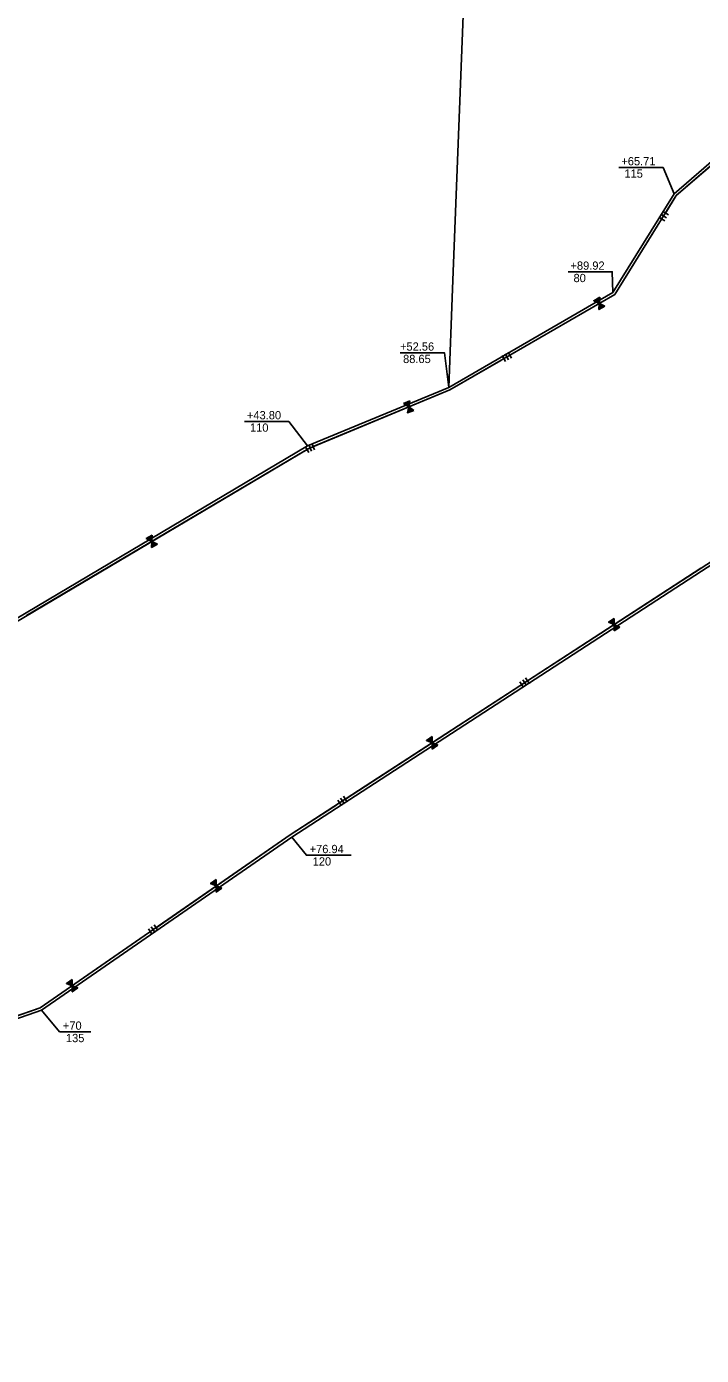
# Model space of a CAD drawing. Extents: x 979729 to 993523, y 1834148 to 1845433.
# Drawn here: x 990587 to 991076, y 1838700 to 1839665 of the extents above; entities that cross this region are included whole.
import ezdxf

# ---------------------------------------------------------------- set-up
doc = ezdxf.new("R2010")
doc.units = 0
for name, color, linetype in [('42', 7, 'Continuous'), ('51', 7, 'Continuous'), ('R_Draft', 7, 'Continuous'), ('S_EXIST_ROW', 7, 'Continuous')]:
    doc.layers.add(name, color=color, linetype=linetype)

msp = doc.modelspace()

# ---------------------------------------------------------------- linework, layer by layer
at = {"layer": '42'}
for p, q in [((991057.83, 1839542.04), (991143.55, 1839616.09)), ((991013.32, 1839470.31), (991057.83, 1839542.04)), ((991046.48, 1839528.48), (991050.73, 1839525.84)), ((991047.8, 1839530.6), (991052.04, 1839527.97)), ((991045.16, 1839526.36), (991049.41, 1839523.72)), ((990893.64, 1839401.08), (991013.32, 1839470.31)), ((990997.95, 1839465.75), (991001.99, 1839463.75)), ((990998.03, 1839465.73), (990998.03, 1839465.8)), ((990998.27, 1839465.63), (990998.29, 1839465.95)), ((990998.51, 1839465.49), (990998.55, 1839466.1)), ((990998.76, 1839465.39), (990998.81, 1839466.25)), ((990999, 1839465.25), (990999.07, 1839466.4)), ((990999.24, 1839465.11), (990999.33, 1839466.55)), ((990999.49, 1839465.01), (990999.59, 1839466.7)), ((990999.73, 1839464.98), (990999.84, 1839466.68)), ((990999.97, 1839464.8), (991000.11, 1839467)), ((991000.22, 1839464.7), (991000.37, 1839467.15)), ((991000.46, 1839464.53), (991000.63, 1839467.3)), ((991000.7, 1839464.46), (991000.89, 1839467.45)), ((991000.94, 1839464.29), (991001.15, 1839467.6)), ((991001.19, 1839464.2), (991001.41, 1839467.75)), ((991001.43, 1839464.05), (991001.67, 1839467.9)), ((991001.67, 1839463.98), (991001.93, 1839468.05)), ((991001.71, 1839459.26), (991001.99, 1839463.75)), ((991001.76, 1839459.87), (991002.31, 1839459.6)), ((991001.76, 1839459.59), (991002.05, 1839459.45)), ((991001.8, 1839460.69), (991003.09, 1839460.06)), ((991001.8, 1839460.41), (991002.83, 1839459.9)), ((991001.8, 1839460.13), (991002.57, 1839459.75)), ((991001.83, 1839460.95), (991003.35, 1839460.21)), ((991001.89, 1839461.48), (991003.87, 1839460.51)), ((991001.9, 1839462.03), (991004.39, 1839460.81)), ((991001.91, 1839463.82), (991002.19, 1839468.2)), ((991001.93, 1839461.74), (991004.13, 1839460.66)), ((991001.93, 1839461.19), (991003.46, 1839460.43)), ((991001.94, 1839462.57), (991004.91, 1839461.11)), ((991001.96, 1839462.28), (991004.65, 1839460.96)), ((991001.97, 1839463.11), (991005.43, 1839461.41)), ((991001.97, 1839462.84), (991005.17, 1839461.26)), ((991001.99, 1839463.75), (991002.28, 1839468.25)), ((991001.99, 1839463.75), (991006.03, 1839461.76)), ((991002.01, 1839463.66), (991005.95, 1839461.71)), ((991002.03, 1839463.36), (991005.69, 1839461.56)), ((991001.73, 1839459.33), (991001.79, 1839459.3)), ((990931.49, 1839425.87), (990933.99, 1839421.54)), ((990933.65, 1839427.12), (990936.16, 1839422.79)), ((990935.82, 1839428.37), (990938.32, 1839424.04)), ((990791.28, 1839358.59), (990893.64, 1839401.08)), ((990861.92, 1839389.99), (990862.34, 1839392.15)), ((990862.14, 1839389.86), (990862.62, 1839392.27)), ((990862.36, 1839389.66), (990862.9, 1839392.38)), ((990862.6, 1839389.56), (990863.17, 1839392.5)), ((990862.81, 1839389.36), (990863.45, 1839392.61)), ((990863.04, 1839389.23), (990863.73, 1839392.73)), ((990863.26, 1839389.06), (990864.01, 1839392.84)), ((990863.49, 1839388.96), (990864.28, 1839392.96)), ((990863.71, 1839388.76), (990864.56, 1839393.07)), ((990863.78, 1839388.69), (990864.65, 1839393.11)), ((990860.04, 1839391.19), (990863.78, 1839388.69)), ((990860.11, 1839391.17), (990860.12, 1839391.23)), ((990860.34, 1839391.04), (990860.4, 1839391.35)), ((990860.56, 1839390.87), (990860.68, 1839391.46)), ((990860.79, 1839390.74), (990860.95, 1839391.58)), ((990861.01, 1839390.57), (990861.23, 1839391.69)), ((990861.23, 1839390.4), (990861.51, 1839391.81)), ((990861.46, 1839390.26), (990861.79, 1839391.92)), ((990861.7, 1839390.2), (990862.03, 1839391.87)), ((990862.91, 1839384.27), (990863.78, 1839388.69)), ((990862.94, 1839384.34), (990863, 1839384.3)), ((990863.01, 1839384.59), (990863.27, 1839384.42)), ((990863.05, 1839384.87), (990863.55, 1839384.53)), ((990863.12, 1839385.13), (990863.83, 1839384.65)), ((990863.15, 1839385.4), (990864.11, 1839384.76)), ((990863.19, 1839385.68), (990864.38, 1839384.88)), ((990863.26, 1839385.93), (990864.66, 1839384.99)), ((990863.38, 1839386.15), (990864.8, 1839385.2)), ((990863.39, 1839386.45), (990865.22, 1839385.23)), ((990863.46, 1839386.7), (990865.49, 1839385.34)), ((990863.47, 1839387), (990865.77, 1839385.46)), ((990863.56, 1839387.24), (990866.05, 1839385.57)), ((990863.57, 1839387.53), (990866.33, 1839385.69)), ((990863.64, 1839387.78), (990866.6, 1839385.8)), ((990863.68, 1839388.06), (990866.88, 1839385.92)), ((990863.77, 1839388.3), (990867.16, 1839386.03)), ((990863.78, 1839388.69), (990867.53, 1839386.19)), ((990863.78, 1839388.59), (990867.44, 1839386.15)), ((990496.48, 1839183.82), (990791.28, 1839358.59)), ((990788.72, 1839359.98), (990791.27, 1839355.68)), ((990791.25, 1839361.28), (990793.16, 1839356.67)), ((990793.55, 1839362.24), (990795.47, 1839357.63)), ((990777.81, 1839078.13), (991153.73, 1839322.34)), ((990677.43, 1839291.14), (990677.67, 1839295.64)), ((990673.37, 1839293.09), (990677.43, 1839291.14)), ((990673.45, 1839293.07), (990673.45, 1839293.13)), ((990673.69, 1839292.97), (990673.71, 1839293.29)), ((990673.93, 1839292.84), (990673.97, 1839293.44)), ((990674.18, 1839292.74), (990674.23, 1839293.59)), ((990674.42, 1839292.6), (990674.48, 1839293.75)), ((990674.67, 1839292.47), (990674.74, 1839293.9)), ((990674.91, 1839292.37), (990675, 1839294.05)), ((990675.16, 1839292.34), (990675.25, 1839294.04)), ((990675.4, 1839292.16), (990675.52, 1839294.36)), ((990675.65, 1839292.06), (990675.78, 1839294.51)), ((990675.89, 1839291.9), (990676.03, 1839294.67)), ((990676.14, 1839291.83), (990676.29, 1839294.82)), ((990676.38, 1839291.66), (990676.55, 1839294.97)), ((990676.62, 1839291.57), (990676.81, 1839295.13)), ((990676.86, 1839291.43), (990677.07, 1839295.28)), ((990677.11, 1839291.36), (990677.33, 1839295.43)), ((990677.19, 1839286.64), (990677.43, 1839291.14)), ((990677.22, 1839286.71), (990677.27, 1839286.68)), ((990677.24, 1839287.25), (990677.79, 1839286.99)), ((990677.25, 1839286.97), (990677.53, 1839286.84)), ((990677.27, 1839288.07), (990678.57, 1839287.45)), ((990677.27, 1839287.79), (990678.31, 1839287.3)), ((990677.28, 1839287.51), (990678.05, 1839287.14)), ((990677.3, 1839288.33), (990678.83, 1839287.6)), ((990677.35, 1839291.2), (990677.58, 1839295.59)), ((990677.36, 1839289.42), (990679.86, 1839288.22)), ((990677.36, 1839288.86), (990679.34, 1839287.91)), ((990677.39, 1839289.96), (990680.38, 1839288.52)), ((990677.39, 1839289.12), (990679.6, 1839288.06)), ((990677.39, 1839288.57), (990678.93, 1839287.83)), ((990677.42, 1839290.5), (990680.89, 1839288.83)), ((990677.42, 1839290.22), (990680.63, 1839288.68)), ((990677.42, 1839289.67), (990680.12, 1839288.37)), ((990677.43, 1839291.14), (990681.5, 1839289.19)), ((990677.45, 1839291.04), (990681.41, 1839289.13)), ((990677.48, 1839290.75), (990681.15, 1839288.98)), ((991008.63, 1839232.55), (991012.77, 1839230.76)), ((991008.7, 1839232.53), (991008.71, 1839232.6)), ((991008.95, 1839232.45), (991008.96, 1839232.76)), ((991009.2, 1839232.32), (991009.21, 1839232.92)), ((991009.45, 1839232.23), (991009.46, 1839233.09)), ((991009.7, 1839232.1), (991009.71, 1839233.25)), ((991009.95, 1839231.98), (991009.97, 1839233.42)), ((991010.2, 1839231.89), (991010.22, 1839233.58)), ((991010.45, 1839231.87), (991010.47, 1839233.58)), ((991010.7, 1839231.7), (991010.72, 1839233.91)), ((991010.94, 1839231.62), (991010.97, 1839234.07)), ((991011.19, 1839231.46), (991011.23, 1839234.23)), ((991011.44, 1839231.4), (991011.48, 1839234.4)), ((991011.69, 1839231.25), (991011.73, 1839234.56)), ((991011.94, 1839231.16), (991011.98, 1839234.73)), ((991012.19, 1839231.03), (991012.23, 1839234.89)), ((991012.44, 1839230.98), (991012.48, 1839235.05)), ((991012.68, 1839230.82), (991012.74, 1839235.22)), ((991012.71, 1839226.26), (991012.77, 1839230.76)), ((991012.76, 1839229.04), (991015.31, 1839227.95)), ((991012.77, 1839230.76), (991012.82, 1839235.27)), ((991012.77, 1839230.76), (991016.91, 1839228.98)), ((991012.77, 1839229.58), (991015.82, 1839228.27)), ((991012.78, 1839230.12), (991016.32, 1839228.6)), ((991012.78, 1839228.49), (991014.81, 1839227.62)), ((991012.79, 1839230.67), (991016.82, 1839228.93)), ((991012.79, 1839229.85), (991016.07, 1839228.44)), ((991012.81, 1839229.29), (991015.56, 1839228.11)), ((991012.81, 1839228.75), (991015.06, 1839227.78)), ((991012.83, 1839230.38), (991016.57, 1839228.76)), ((991012.83, 1839228.2), (991014.4, 1839227.52)), ((991012.73, 1839227.7), (991014.05, 1839227.13)), ((991012.73, 1839226.33), (991012.79, 1839226.31)), ((991012.74, 1839227.42), (991013.8, 1839226.96)), ((991012.74, 1839226.88), (991013.3, 1839226.64)), ((991012.75, 1839227.96), (991014.3, 1839227.29)), ((991012.75, 1839226.6), (991013.04, 1839226.47)), ((991012.76, 1839227.14), (991013.55, 1839226.8)), ((990946.42, 1839190.64), (990949.14, 1839186.45)), ((990948.51, 1839192), (990951.24, 1839187.81)), ((990944.32, 1839189.28), (990947.04, 1839185.08)), ((990876.55, 1839146.74), (990880.69, 1839144.96)), ((990876.63, 1839146.73), (990876.63, 1839146.79)), ((990876.88, 1839146.64), (990876.88, 1839146.96)), ((990877.13, 1839146.51), (990877.13, 1839147.12)), ((990877.38, 1839146.43), (990877.39, 1839147.29)), ((990877.62, 1839146.3), (990877.64, 1839147.45)), ((990877.87, 1839146.18), (990877.89, 1839147.61)), ((990878.12, 1839146.09), (990878.14, 1839147.78)), ((990878.37, 1839146.07), (990878.39, 1839147.77)), ((990878.62, 1839145.9), (990878.65, 1839148.1)), ((990878.87, 1839145.81), (990878.9, 1839148.27)), ((990879.12, 1839145.66), (990879.15, 1839148.43)), ((990879.37, 1839145.6), (990879.4, 1839148.6)), ((990879.61, 1839145.45), (990879.65, 1839148.76)), ((990879.86, 1839145.36), (990879.9, 1839148.92)), ((990880.11, 1839145.23), (990880.16, 1839149.09)), ((990880.36, 1839145.17), (990880.41, 1839149.25)), ((990880.61, 1839145.02), (990880.66, 1839149.41)), ((990880.64, 1839140.45), (990880.69, 1839144.96)), ((990880.65, 1839141.89), (990881.98, 1839141.32)), ((990880.67, 1839141.61), (990881.72, 1839141.16)), ((990880.68, 1839142.16), (990882.23, 1839141.49)), ((990880.68, 1839141.34), (990881.47, 1839141)), ((990880.69, 1839144.96), (990880.74, 1839149.47)), ((990880.69, 1839144.96), (990884.83, 1839143.18)), ((990880.69, 1839143.24), (990883.24, 1839142.14)), ((990880.7, 1839144.32), (990884.24, 1839142.8)), ((990880.7, 1839143.78), (990883.74, 1839142.47)), ((990880.71, 1839144.86), (990884.75, 1839143.12)), ((990880.71, 1839142.69), (990882.73, 1839141.81)), ((990880.72, 1839144.04), (990883.99, 1839142.63)), ((990880.73, 1839142.95), (990882.98, 1839141.98)), ((990880.74, 1839143.49), (990883.49, 1839142.31)), ((990880.75, 1839144.57), (990884.49, 1839142.96)), ((990880.76, 1839142.39), (990882.33, 1839141.72)), ((990880.66, 1839141.07), (990881.22, 1839140.83)), ((990880.66, 1839140.53), (990880.72, 1839140.5)), ((990880.68, 1839140.79), (990880.97, 1839140.67)), ((990812.24, 1839103.47), (990814.97, 1839099.28)), ((990814.34, 1839104.84), (990817.06, 1839100.64)), ((990816.44, 1839106.2), (990819.16, 1839102.01)), ((990596.51, 1838952.77), (990777.81, 1839078.13)), ((990723.01, 1839041.62), (990722.95, 1839044.93)), ((990723.26, 1839041.54), (990723.2, 1839045.1)), ((990723.51, 1839041.42), (990723.45, 1839045.27)), ((990723.76, 1839041.37), (990723.7, 1839045.44)), ((990724.02, 1839041.22), (990723.94, 1839045.61)), ((990724.1, 1839041.17), (990724.02, 1839045.67)), ((990719.91, 1839042.83), (990724.1, 1839041.17)), ((990719.99, 1839042.82), (990719.99, 1839042.88)), ((990720.24, 1839042.74), (990720.24, 1839043.05)), ((990720.49, 1839042.62), (990720.48, 1839043.22)), ((990720.75, 1839042.54), (990720.73, 1839043.39)), ((990721, 1839042.42), (990720.98, 1839043.56)), ((990721.25, 1839042.3), (990721.22, 1839043.74)), ((990721.5, 1839042.22), (990721.47, 1839043.91)), ((990721.75, 1839042.2), (990721.72, 1839043.91)), ((990722, 1839042.05), (990721.97, 1839044.25)), ((990722.25, 1839041.97), (990722.21, 1839044.42)), ((990722.51, 1839041.82), (990722.46, 1839044.59)), ((990722.76, 1839041.77), (990722.71, 1839044.76)), ((990724.1, 1839041.17), (990728.29, 1839039.5)), ((990724.18, 1839036.66), (990724.1, 1839041.17)), ((990724.12, 1839041.07), (990728.21, 1839039.45)), ((990724.13, 1839040.53), (990727.71, 1839039.1)), ((990724.14, 1839039.99), (990727.22, 1839038.76)), ((990724.15, 1839040.25), (990727.47, 1839038.93)), ((990724.15, 1839039.44), (990726.73, 1839038.42)), ((990724.15, 1839038.1), (990725.49, 1839037.57)), ((990724.17, 1839040.78), (990727.96, 1839039.28)), ((990724.17, 1839038.36), (990725.74, 1839037.74)), ((990724.17, 1839037.82), (990725.24, 1839037.4)), ((990724.18, 1839038.89), (990726.23, 1839038.08)), ((990724.18, 1839037.28), (990724.75, 1839037.05)), ((990724.19, 1839039.7), (990726.97, 1839038.59)), ((990724.19, 1839036.74), (990724.25, 1839036.71)), ((990724.2, 1839039.16), (990726.48, 1839038.25)), ((990724.2, 1839037.54), (990725, 1839037.22)), ((990724.21, 1839037), (990724.5, 1839036.88)), ((990724.24, 1839038.6), (990725.83, 1839037.97)), ((990674.94, 1839010.04), (990677.79, 1839005.93)), ((990677, 1839011.46), (990679.84, 1839007.35)), ((990679.06, 1839012.88), (990681.9, 1839008.77)), ((990615.43, 1838970.42), (990619.62, 1838968.75)), ((990615.51, 1838970.4), (990615.51, 1838970.47)), ((990615.76, 1838970.33), (990615.76, 1838970.64)), ((990616.01, 1838970.2), (990616, 1838970.81)), ((990616.27, 1838970.13), (990616.25, 1838970.98)), ((990616.52, 1838970), (990616.5, 1838971.15)), ((990616.77, 1838969.89), (990616.75, 1838971.32)), ((990617.02, 1838969.81), (990616.99, 1838971.49)), ((990617.27, 1838969.79), (990617.24, 1838971.5)), ((990617.53, 1838969.63), (990617.49, 1838971.84)), ((990617.78, 1838969.55), (990617.74, 1838972.01)), ((990618.03, 1838969.41), (990617.98, 1838972.18)), ((990618.28, 1838969.36), (990618.23, 1838972.35)), ((990618.53, 1838969.21), (990618.48, 1838972.52)), ((990618.78, 1838969.13), (990618.72, 1838972.69)), ((990619.04, 1838969.01), (990618.97, 1838972.86)), ((990619.29, 1838968.96), (990619.22, 1838973.03)), ((990619.54, 1838968.81), (990619.46, 1838973.2)), ((990619.62, 1838968.75), (990619.55, 1838973.26)), ((990619.62, 1838968.75), (990623.81, 1838967.09)), ((990619.7, 1838964.25), (990619.62, 1838968.75)), ((990619.64, 1838968.66), (990623.73, 1838967.03)), ((990619.65, 1838968.11), (990623.24, 1838966.69)), ((990619.68, 1838967.84), (990622.99, 1838966.52)), ((990619.69, 1838968.37), (990623.48, 1838966.86)), ((990619.66, 1838967.57), (990622.74, 1838966.35)), ((990619.67, 1838967.03), (990622.25, 1838966.01)), ((990619.68, 1838965.68), (990621.01, 1838965.15)), ((990619.69, 1838965.95), (990621.26, 1838965.33)), ((990619.7, 1838965.41), (990620.76, 1838964.98)), ((990619.71, 1838967.29), (990622.5, 1838966.18)), ((990619.71, 1838966.48), (990621.75, 1838965.67)), ((990619.71, 1838964.87), (990620.27, 1838964.64)), ((990619.71, 1838964.32), (990619.78, 1838964.3)), ((990619.72, 1838966.74), (990622, 1838965.84)), ((990619.72, 1838965.13), (990620.52, 1838964.81)), ((990619.73, 1838964.59), (990620.02, 1838964.47)), ((990619.76, 1838966.19), (990621.35, 1838965.56)), ((990106.16, 1838781.5), (990596.51, 1838952.77))]:
    msp.add_line(p, q, dxfattribs=at)
for points in [[(991049.92, 1839529.29), (991057.83, 1839542.04), (991143.55, 1839616.09), (991151.55, 1839620.15)], [(990937.07, 1839426.2), (991013.32, 1839470.31), (991045.97, 1839522.91)], [(990997.95, 1839465.75), (991002.28, 1839468.25)], [(991001.71, 1839459.26), (991006.03, 1839461.76)], [(990794.51, 1839359.93), (990893.64, 1839401.08), (990930.58, 1839422.45)], [(990860.04, 1839391.19), (990864.65, 1839393.11)], [(990862.91, 1839384.27), (990867.53, 1839386.19)], [(990586.6, 1839237.25), (990787.84, 1839356.55)], [(990673.37, 1839293.09), (990677.67, 1839295.64)], [(990677.19, 1839286.64), (990681.5, 1839289.19)], [(990949.87, 1839189.91), (991075.66, 1839271.62)], [(991008.63, 1839232.55), (991012.82, 1839235.27)], [(991012.71, 1839226.26), (991016.91, 1839228.98)], [(990817.8, 1839104.1), (990943.58, 1839185.82)], [(990876.55, 1839146.74), (990880.74, 1839149.47)], [(990880.64, 1839140.45), (990884.83, 1839143.18)], [(990742.33, 1839053.59), (990777.81, 1839078.13), (990811.51, 1839100.02)], [(990680.48, 1839010.83), (990777.81, 1839078.13)], [(990719.91, 1839042.83), (990724.02, 1839045.67)], [(990724.18, 1839036.66), (990728.29, 1839039.5)], [(990552.23, 1838937.31), (990596.51, 1838952.77), (990675.14, 1839007.14)], [(990615.43, 1838970.42), (990619.55, 1838973.26)], [(990619.7, 1838964.25), (990623.81, 1838967.09)]]:
    msp.add_lwpolyline(points, dxfattribs=at)
at = {"layer": '51'}
for p, q in [((991056.3, 1839543.35), (991011.89, 1839471.79)), ((991011.89, 1839471.79), (990892.75, 1839402.88)), ((990790.39, 1839360.39), (990892.75, 1839402.88))]:
    msp.add_line(p, q, dxfattribs=at)
for points in [[(991218.79, 1839656.57), (991142.43, 1839617.76), (991056.3, 1839543.35)], [(991319.91, 1839393.75), (991154.69, 1839320.58), (990778.93, 1839076.47)], [(990790.39, 1839360.39), (990495.54, 1839185.59), (990219.53, 1839055.3), (989873.17, 1838970.64), (989662.61, 1838927.17), (989537.01, 1838942.08), (989341.14, 1838901.64), (989234.92, 1838854.19)], [(990778.93, 1839076.47), (990597.42, 1838950.97), (990030.44, 1838752.94), (989776.33, 1838700.48)]]:
    msp.add_lwpolyline(points, dxfattribs=at)
at = {"layer": 'R_Draft'}
for p, q in [((991016.18, 1839562.47), (991042.22, 1839562.47)), ((990979.29, 1839486.71), (991005.33, 1839486.71)), ((990857.54, 1839427.99), (990883.58, 1839427.99)), ((990744.65, 1839378.18), (990770.69, 1839378.18)), ((990795.5, 1839063.42), (990822.08, 1839063.42)), ((990616.53, 1838935.27), (990633.29, 1838935.27))]:
    msp.add_line(p, q, dxfattribs=at)
for points in [[(991056.3, 1839543.35), (991048.22, 1839562.47), (991042.22, 1839562.47)], [(991011.89, 1839471.79), (991011.33, 1839486.71), (991005.33, 1839486.71)], [(990892.75, 1839402.88), (990889.58, 1839427.99), (990883.58, 1839427.99)], [(990790.39, 1839360.39), (990776.69, 1839378.18), (990770.69, 1839378.18)], [(990778.93, 1839076.47), (990789.5, 1839063.42), (990795.5, 1839063.42)], [(990597.42, 1838950.97), (990610.53, 1838935.27), (990616.53, 1838935.27)]]:
    msp.add_lwpolyline(points, dxfattribs=at)
at = {"layer": 'S_EXIST_ROW'}
for p, q in [((990903.18, 1839672.71), (990901.26, 1839623.11)), ((990901.26, 1839623.11), (990899.35, 1839573.51)), ((990899.35, 1839573.51), (990897.43, 1839523.91)), ((990897.43, 1839523.91), (990895.51, 1839474.31)), ((990895.51, 1839474.31), (990892.75, 1839402.88))]:
    msp.add_line(p, q, dxfattribs=at)

# ---------------------------------------------------------------- texts
at = {"layer": 'R_Draft'}
for s, p in [('+65.71', (991017.95, 1839563.97)), (' 115', (991017.95, 1839554.97)), ('+89.92', (990981.06, 1839488.21)), (' 80', (990981.06, 1839479.21)), ('+52.56', (990857.43, 1839429.49)), (' 88.65', (990857.43, 1839420.49)), ('+43.80', (990746.42, 1839379.68)), (' 110', (990746.42, 1839370.68)), ('+76.94', (990791.88, 1839064.92)), (' 120', (990791.88, 1839055.92)), ('+70', (990612.91, 1838936.77)), (' 135', (990612.91, 1838927.77))]:
    msp.add_text(s, height=6, rotation=360, dxfattribs=at).set_placement(p)

doc.saveas('drawing.dxf')
